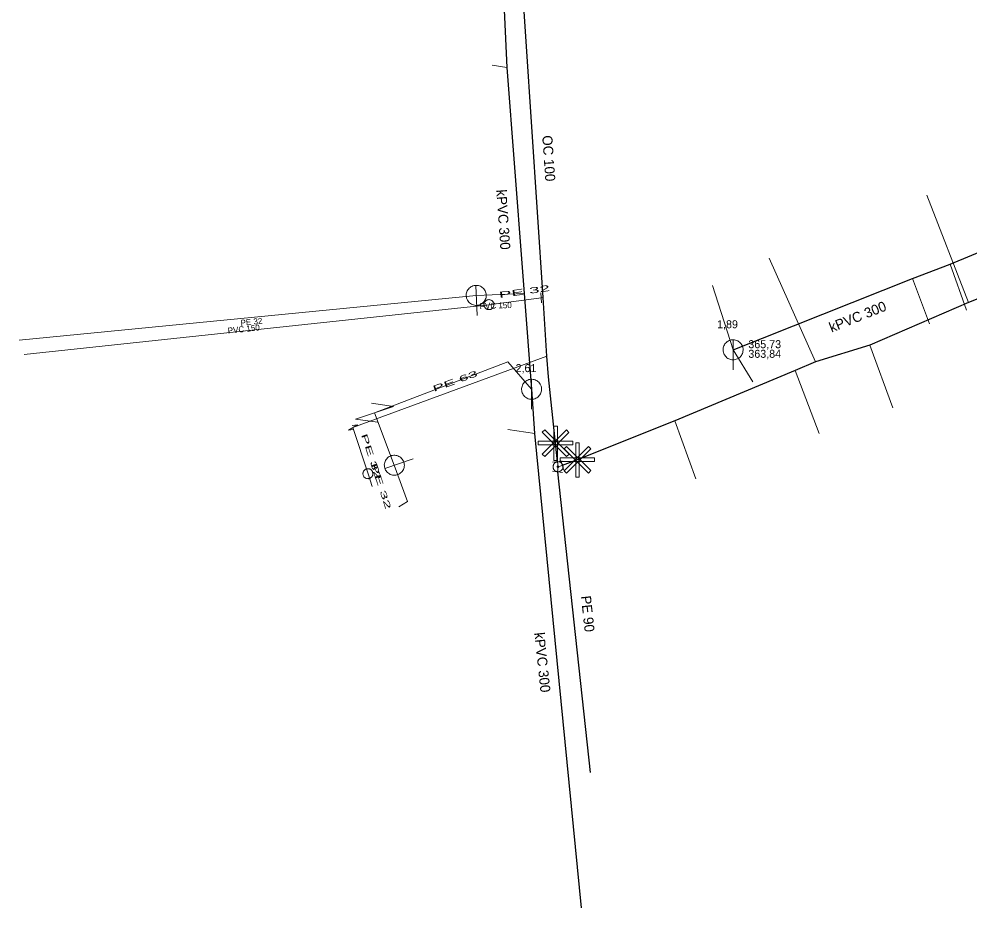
# Model space of a CAD drawing. Extents: x -809916 to -809489, y -991143 to -990912.
# Drawn here: x -809716.9 to -809621.9, y -991094.3 to -991005.4 of the extents above; entities that cross this region are included whole.
import ezdxf

# ---------------------------------------------------------------- set-up
doc = ezdxf.new("R2010")
doc.units = 0
doc.header["$LTSCALE"] = 0.32
doc.layers.add('1', color=7, linetype='Continuous')
for name, color, linetype, lineweight in [('11', 7, 'Continuous', 13), ('12', 7, 'Continuous', 13), ('13', 7, 'Continuous', 13), ('14', 7, 'Continuous', 25), ('17', 7, 'Continuous', 25), ('19', 7, 'Continuous', 13), ('22', 7, 'Continuous', 13), ('23', 7, 'Continuous', 13), ('31', 7, 'Continuous', 13), ('34', 7, 'Continuous', 13), ('47', 7, 'Continuous', 13)]:
    doc.layers.add(name, color=color, linetype=linetype, lineweight=lineweight)

msp = doc.modelspace()

# ---------------------------------------------------------------- linework, layer by layer
at = {"layer": '11'}
for p, q in [((-809669.64, -991010.07), (-809668.193, -991010.278)), ((-809622.243, -991034.537), (-809623.903, -991029.949)), ((-809625.96, -991035.892), (-809627.638, -991031.374)), ((-809647.623, -991032.088), (-809645.575, -991038.5)), ((-809716.921, -991037.548), (-809671.24, -991033.063)), ((-809671.24, -991033.063), (-809666.449, -991032.861)), ((-809643.62, -991041.703), (-809645.575, -991038.5)), ((-809679.424, -991050.034), (-809681.405, -991044.785)), ((-809668.083, -991046.469), (-809665.401, -991046.877))]:
    msp.add_line(p, q, dxfattribs=at)
for points in [[(-809681.405, -991044.785), (-809668.079, -991039.712), (-809665.71, -991042.44)], [(-809678.962, -991054.193), (-809678.104, -991053.665), (-809679.424, -991050.034)]]:
    msp.add_lwpolyline(points, dxfattribs=at)
at = {"layer": '12'}
for points in [[(-809662.22, -991046.499), (-809661.972, -991046.747), (-809664.401, -991049.176), (-809664.647, -991048.928)], [(-809664.639, -991046.738), (-809664.392, -991046.49), (-809661.963, -991048.919), (-809662.21, -991049.167)], [(-809663.486, -991046.135), (-809663.136, -991046.135), (-809663.136, -991049.57), (-809663.486, -991049.57)], [(-809661.602, -991047.644), (-809661.602, -991047.994), (-809665.037, -991047.994), (-809665.037, -991047.644)], [(-809661.301, -991047.791), (-809660.951, -991047.791), (-809660.951, -991051.226), (-809661.301, -991051.226)], [(-809660.035, -991048.155), (-809659.787, -991048.403), (-809662.216, -991050.832), (-809662.463, -991050.584)], [(-809662.454, -991048.394), (-809662.207, -991048.146), (-809659.778, -991050.575), (-809660.025, -991050.823)], [(-809659.417, -991049.3), (-809659.417, -991049.65), (-809662.852, -991049.65), (-809662.852, -991049.3)]]:
    msp.add_lwpolyline(points, close=True, dxfattribs=at)
at = {"layer": '13'}
for p, q in [((-809622.052, -991033.77), (-809626.208, -991023.049)), ((-809637.348, -991039.711), (-809641.962, -991029.357)), ((-809664.752, -991033.305), (-809669.989, -991034.015)), ((-809669.989, -991034.015), (-809716.423, -991038.976)), ((-809631.922, -991038.029), (-809629.608, -991044.298)), ((-809639.388, -991040.574), (-809636.96, -991046.859)), ((-809651.392, -991045.595), (-809649.291, -991051.397))]:
    msp.add_line(p, q, dxfattribs=at)
msp.add_lwpolyline([(-809664.17, -991039.14), (-809683.557, -991046.261), (-809682.032, -991050.892), (-809681.636, -991052.146)], dxfattribs=at)
at = {"layer": '14', "lineweight": 13}
for p, q in [((-809664.559, -991033.289), (-809664.752, -991033.305)), ((-809663.069, -991050.189), (-809663.12, -991049.689)), ((-809663.069, -991050.189), (-809663.129, -991050.689)), ((-809663.069, -991050.189), (-809662.639, -991050.049))]:
    msp.add_line(p, q, dxfattribs=at)
at = {"layer": '14'}
for points in [[(-809668.578, -991001.644), (-809668.193, -991010.278), (-809666.649, -991030.266), (-809666.449, -991032.861), (-809665.71, -991042.44)], [(-809645.575, -991038.5), (-809627.638, -991031.374), (-809623.903, -991029.949), (-809619.972, -991028.327)], [(-809665.71, -991042.44), (-809665.402, -991046.877), (-809660.74, -991094.27)]]:
    msp.add_lwpolyline(points, dxfattribs=at)
at = {"layer": '17'}
msp.add_line((-809663.129, -991050.689), (-809659.85, -991080.729), dxfattribs=at)
for points in [[(-809663.12, -991049.689), (-809663.328, -991047.82), (-809664.033, -991041.203), (-809664.17, -991039.14), (-809664.559, -991033.289), (-809666.831, -990999.127), (-809667.227, -990980.191), (-809667.463, -990975.798), (-809668.285, -990965.145), (-809668.606, -990961.097)], [(-809566.909, -991012.119), (-809584.614, -991018.942), (-809585.199, -991019.149), (-809592.769, -991022.094), (-809597, -991024.013), (-809605.64, -991027.482), (-809607.317, -991028.215), (-809616.081, -991031.412), (-809622.052, -991033.77), (-809631.921, -991038.028), (-809637.348, -991039.71), (-809639.388, -991040.574), (-809651.392, -991045.594), (-809661.144, -991049.477), (-809662.639, -991050.049)]]:
    msp.add_lwpolyline(points, dxfattribs=at)
at = {"layer": '22'}
for p, q in [((-809671.156, -991035.061), (-809671.281, -991032.064)), ((-809645.575, -991040.5), (-809645.574, -991037.5)), ((-809665.71, -991044.44), (-809665.709, -991041.44)), ((-809677.525, -991049.404), (-809680.372, -991050.348))]:
    msp.add_line(p, q, dxfattribs=at)
for points in [[(-809670.24, -991033.021), (-809670.251, -991032.912), (-809670.273, -991032.805), (-809670.308, -991032.701), (-809670.352, -991032.601), (-809670.408, -991032.507), (-809670.474, -991032.419), (-809670.549, -991032.339), (-809670.632, -991032.269), (-809670.723, -991032.207), (-809670.819, -991032.156), (-809670.921, -991032.115), (-809671.027, -991032.086), (-809671.135, -991032.069), (-809671.244, -991032.063), (-809671.354, -991032.07), (-809671.462, -991032.088), (-809671.567, -991032.118), (-809671.669, -991032.159), (-809671.765, -991032.212), (-809671.854, -991032.274), (-809671.937, -991032.347), (-809672.011, -991032.427), (-809672.076, -991032.516), (-809672.131, -991032.61), (-809672.175, -991032.71), (-809672.208, -991032.814), (-809672.229, -991032.922), (-809672.239, -991033.031), (-809672.236, -991033.141), (-809672.222, -991033.249), (-809672.196, -991033.355), (-809672.158, -991033.458), (-809672.11, -991033.556), (-809672.051, -991033.649), (-809671.981, -991033.734), (-809671.904, -991033.811), (-809671.818, -991033.879), (-809671.725, -991033.937), (-809671.627, -991033.985), (-809671.524, -991034.022), (-809671.417, -991034.047), (-809671.309, -991034.061), (-809671.199, -991034.062), (-809671.09, -991034.052), (-809670.983, -991034.029), (-809670.879, -991033.996), (-809670.779, -991033.95), (-809670.684, -991033.894), (-809670.597, -991033.829), (-809670.517, -991033.754), (-809670.445, -991033.671), (-809670.384, -991033.581), (-809670.332, -991033.484), (-809670.292, -991033.383), (-809670.263, -991033.277), (-809670.245, -991033.168), (-809670.24, -991033.059)], [(-809644.575, -991038.5), (-809644.58, -991038.391), (-809644.598, -991038.283), (-809644.628, -991038.177), (-809644.668, -991038.076), (-809644.72, -991037.979), (-809644.782, -991037.889), (-809644.854, -991037.806), (-809644.934, -991037.732), (-809645.022, -991037.666), (-809645.116, -991037.611), (-809645.216, -991037.566), (-809645.321, -991037.533), (-809645.428, -991037.511), (-809645.537, -991037.501), (-809645.647, -991037.503), (-809645.755, -991037.517), (-809645.862, -991037.542), (-809645.965, -991037.579), (-809646.063, -991037.628), (-809646.155, -991037.686), (-809646.241, -991037.755), (-809646.318, -991037.832), (-809646.387, -991037.918), (-809646.446, -991038.01), (-809646.494, -991038.108), (-809646.531, -991038.211), (-809646.557, -991038.318), (-809646.571, -991038.426), (-809646.574, -991038.536), (-809646.564, -991038.645), (-809646.543, -991038.752), (-809646.509, -991038.856), (-809646.465, -991038.956), (-809646.41, -991039.051), (-809646.344, -991039.139), (-809646.27, -991039.219), (-809646.187, -991039.291), (-809646.097, -991039.353), (-809646.001, -991039.405), (-809645.899, -991039.446), (-809645.794, -991039.476), (-809645.686, -991039.494), (-809645.576, -991039.5), (-809645.467, -991039.494), (-809645.359, -991039.476), (-809645.254, -991039.447), (-809645.152, -991039.406), (-809645.055, -991039.354), (-809644.965, -991039.292), (-809644.882, -991039.221), (-809644.807, -991039.141), (-809644.742, -991039.053), (-809644.686, -991038.959), (-809644.642, -991038.859), (-809644.608, -991038.755), (-809644.586, -991038.647), (-809644.576, -991038.538)], [(-809664.71, -991042.44), (-809664.715, -991042.331), (-809664.733, -991042.223), (-809664.763, -991042.117), (-809664.803, -991042.016), (-809664.855, -991041.919), (-809664.917, -991041.829), (-809664.989, -991041.746), (-809665.069, -991041.672), (-809665.157, -991041.606), (-809665.251, -991041.551), (-809665.351, -991041.506), (-809665.456, -991041.473), (-809665.563, -991041.451), (-809665.672, -991041.441), (-809665.782, -991041.443), (-809665.89, -991041.457), (-809665.997, -991041.482), (-809666.1, -991041.519), (-809666.198, -991041.568), (-809666.29, -991041.626), (-809666.376, -991041.695), (-809666.453, -991041.772), (-809666.522, -991041.858), (-809666.581, -991041.95), (-809666.629, -991042.048), (-809666.666, -991042.151), (-809666.692, -991042.258), (-809666.706, -991042.366), (-809666.709, -991042.476), (-809666.699, -991042.585), (-809666.678, -991042.692), (-809666.644, -991042.796), (-809666.6, -991042.896), (-809666.545, -991042.991), (-809666.479, -991043.079), (-809666.405, -991043.159), (-809666.322, -991043.231), (-809666.232, -991043.293), (-809666.136, -991043.345), (-809666.034, -991043.386), (-809665.929, -991043.416), (-809665.821, -991043.434), (-809665.711, -991043.44), (-809665.602, -991043.434), (-809665.494, -991043.416), (-809665.389, -991043.387), (-809665.287, -991043.346), (-809665.19, -991043.294), (-809665.1, -991043.232), (-809665.017, -991043.161), (-809664.942, -991043.081), (-809664.877, -991042.993), (-809664.821, -991042.899), (-809664.777, -991042.799), (-809664.743, -991042.695), (-809664.721, -991042.587), (-809664.711, -991042.478)], [(-809679.738, -991049.084), (-809679.839, -991049.124), (-809679.936, -991049.175), (-809680.027, -991049.237), (-809680.111, -991049.307), (-809680.186, -991049.387), (-809680.252, -991049.474), (-809680.308, -991049.568), (-809680.353, -991049.668), (-809680.388, -991049.772), (-809680.411, -991049.878), (-809680.422, -991049.988), (-809680.421, -991050.098), (-809680.408, -991050.206), (-809680.383, -991050.313), (-809680.346, -991050.416), (-809680.299, -991050.515), (-809680.242, -991050.608), (-809680.174, -991050.694), (-809680.097, -991050.772), (-809680.013, -991050.841), (-809679.92, -991050.901), (-809679.823, -991050.95), (-809679.72, -991050.988), (-809679.614, -991051.015), (-809679.506, -991051.03), (-809679.396, -991051.033), (-809679.286, -991051.024), (-809679.179, -991051.003), (-809679.074, -991050.97), (-809678.974, -991050.926), (-809678.879, -991050.873), (-809678.791, -991050.808), (-809678.71, -991050.735), (-809678.637, -991050.652), (-809678.574, -991050.562), (-809678.522, -991050.467), (-809678.48, -991050.365), (-809678.449, -991050.26), (-809678.43, -991050.153), (-809678.423, -991050.043), (-809678.428, -991049.934), (-809678.445, -991049.826), (-809678.474, -991049.72), (-809678.514, -991049.618), (-809678.565, -991049.521), (-809678.625, -991049.431), (-809678.696, -991049.347), (-809678.776, -991049.271), (-809678.863, -991049.205), (-809678.957, -991049.149), (-809679.056, -991049.103), (-809679.16, -991049.069), (-809679.267, -991049.045), (-809679.376, -991049.035), (-809679.485, -991049.035), (-809679.595, -991049.048), (-809679.701, -991049.073)]]:
    msp.add_lwpolyline(points, close=True, dxfattribs=at)
at = {"layer": '23'}
for points in [[(-809669.737, -991033.546), (-809669.784, -991033.524), (-809669.834, -991033.508), (-809669.884, -991033.495), (-809669.938, -991033.49), (-809669.989, -991033.49), (-809670.041, -991033.494), (-809670.092, -991033.505), (-809670.142, -991033.52), (-809670.191, -991033.541), (-809670.236, -991033.567), (-809670.279, -991033.597), (-809670.318, -991033.631), (-809670.353, -991033.671), (-809670.385, -991033.712), (-809670.411, -991033.756), (-809670.434, -991033.805), (-809670.45, -991033.855), (-809670.461, -991033.906), (-809670.466, -991033.958), (-809670.468, -991034.009), (-809670.464, -991034.061), (-809670.453, -991034.113), (-809670.438, -991034.164), (-809670.416, -991034.21), (-809670.391, -991034.256), (-809670.361, -991034.299), (-809670.325, -991034.338), (-809670.287, -991034.373), (-809670.245, -991034.404), (-809670.2, -991034.431), (-809670.153, -991034.453), (-809670.103, -991034.471), (-809670.051, -991034.482), (-809670, -991034.488), (-809669.948, -991034.488), (-809669.897, -991034.484), (-809669.844, -991034.473), (-809669.795, -991034.458), (-809669.746, -991034.436)], [(-809670.464, -991034.061), (-809670.453, -991034.113), (-809670.438, -991034.164), (-809670.416, -991034.21), (-809670.391, -991034.256), (-809670.361, -991034.299), (-809670.325, -991034.338), (-809670.287, -991034.373), (-809670.245, -991034.404), (-809670.2, -991034.431), (-809670.153, -991034.453), (-809670.103, -991034.471), (-809670.051, -991034.482), (-809670, -991034.488), (-809669.948, -991034.488), (-809669.897, -991034.484), (-809669.844, -991034.473), (-809669.795, -991034.458), (-809669.746, -991034.436), (-809669.701, -991034.412), (-809669.658, -991034.382), (-809669.619, -991034.345), (-809669.583, -991034.307), (-809669.552, -991034.265), (-809669.525, -991034.22), (-809669.504, -991034.173), (-809669.487, -991034.123), (-809669.476, -991034.073), (-809669.47, -991034.02), (-809669.47, -991033.968), (-809669.474, -991033.916), (-809669.484, -991033.865), (-809669.5, -991033.814), (-809669.521, -991033.766), (-809669.546, -991033.721), (-809669.577, -991033.68), (-809669.611, -991033.64), (-809669.65, -991033.604), (-809669.692, -991033.572), (-809669.737, -991033.546)], [(-809669.746, -991034.436), (-809669.701, -991034.412), (-809669.658, -991034.382), (-809669.619, -991034.345), (-809669.583, -991034.307), (-809669.552, -991034.265), (-809669.525, -991034.22), (-809669.504, -991034.173), (-809669.487, -991034.123), (-809669.476, -991034.073), (-809669.47, -991034.02), (-809669.47, -991033.968), (-809669.474, -991033.916), (-809669.484, -991033.865), (-809669.5, -991033.814), (-809669.521, -991033.766), (-809669.546, -991033.721), (-809669.577, -991033.68), (-809669.611, -991033.64), (-809669.65, -991033.604), (-809669.692, -991033.572), (-809669.737, -991033.546), (-809669.784, -991033.524), (-809669.834, -991033.508), (-809669.884, -991033.495), (-809669.938, -991033.49), (-809669.989, -991033.49), (-809670.041, -991033.494), (-809670.092, -991033.505), (-809670.142, -991033.52), (-809670.191, -991033.541), (-809670.236, -991033.567), (-809670.279, -991033.597), (-809670.318, -991033.631), (-809670.353, -991033.671), (-809670.385, -991033.712), (-809670.411, -991033.756), (-809670.434, -991033.805), (-809670.45, -991033.855), (-809670.461, -991033.906)], [(-809670.461, -991033.906), (-809670.466, -991033.958), (-809670.468, -991034.009), (-809670.464, -991034.061)], [(-809681.663, -991050.573), (-809681.695, -991050.535), (-809681.733, -991050.498), (-809681.776, -991050.466), (-809681.82, -991050.439), (-809681.868, -991050.416), (-809681.917, -991050.397), (-809681.967, -991050.386), (-809682.02, -991050.379), (-809682.071, -991050.377), (-809682.124, -991050.381), (-809682.175, -991050.391), (-809682.225, -991050.405), (-809682.274, -991050.424), (-809682.32, -991050.449), (-809682.364, -991050.479), (-809682.403, -991050.512), (-809682.438, -991050.55), (-809682.471, -991050.592), (-809682.499, -991050.636), (-809682.522, -991050.684), (-809682.539, -991050.733), (-809682.552, -991050.783), (-809682.558, -991050.836), (-809682.561, -991050.887), (-809682.556, -991050.94), (-809682.546, -991050.991), (-809682.532, -991051.041), (-809682.512, -991051.089), (-809682.488, -991051.136), (-809682.458, -991051.18), (-809682.424, -991051.219), (-809682.386, -991051.256), (-809682.346, -991051.288), (-809682.3, -991051.314), (-809682.254, -991051.338), (-809682.205, -991051.355), (-809682.153, -991051.368), (-809682.101, -991051.375), (-809682.049, -991051.376)], [(-809682.539, -991050.733), (-809682.552, -991050.783), (-809682.558, -991050.836), (-809682.561, -991050.887), (-809682.556, -991050.94), (-809682.546, -991050.991), (-809682.532, -991051.041), (-809682.512, -991051.089), (-809682.488, -991051.136), (-809682.458, -991051.18), (-809682.424, -991051.219), (-809682.386, -991051.256), (-809682.346, -991051.288), (-809682.3, -991051.314), (-809682.254, -991051.338), (-809682.205, -991051.355), (-809682.153, -991051.368), (-809682.101, -991051.375), (-809682.049, -991051.376), (-809681.997, -991051.372), (-809681.946, -991051.363), (-809681.896, -991051.349), (-809681.847, -991051.329), (-809681.8, -991051.304), (-809681.759, -991051.274), (-809681.718, -991051.241), (-809681.682, -991051.203), (-809681.65, -991051.161), (-809681.623, -991051.117), (-809681.6, -991051.07), (-809681.582, -991051.021), (-809681.57, -991050.97), (-809681.562, -991050.918), (-809681.561, -991050.865), (-809681.565, -991050.813), (-809681.574, -991050.763), (-809681.588, -991050.713), (-809681.609, -991050.663), (-809681.632, -991050.618), (-809681.663, -991050.573)], [(-809681.896, -991051.349), (-809681.847, -991051.329), (-809681.8, -991051.304), (-809681.759, -991051.274), (-809681.718, -991051.241), (-809681.682, -991051.203), (-809681.65, -991051.161), (-809681.623, -991051.117), (-809681.6, -991051.07), (-809681.582, -991051.021), (-809681.57, -991050.97), (-809681.562, -991050.918), (-809681.561, -991050.865), (-809681.565, -991050.813), (-809681.574, -991050.763), (-809681.588, -991050.713), (-809681.609, -991050.663), (-809681.632, -991050.618), (-809681.663, -991050.573), (-809681.695, -991050.535), (-809681.733, -991050.498), (-809681.776, -991050.466), (-809681.82, -991050.439), (-809681.868, -991050.416), (-809681.917, -991050.397), (-809681.967, -991050.386), (-809682.02, -991050.379), (-809682.071, -991050.377), (-809682.124, -991050.381), (-809682.175, -991050.391), (-809682.225, -991050.405), (-809682.274, -991050.424), (-809682.32, -991050.449), (-809682.364, -991050.479), (-809682.403, -991050.512), (-809682.438, -991050.55), (-809682.471, -991050.592), (-809682.499, -991050.636), (-809682.522, -991050.684), (-809682.539, -991050.733)], [(-809682.049, -991051.376), (-809681.997, -991051.372), (-809681.946, -991051.363), (-809681.896, -991051.349)]]:
    msp.add_lwpolyline(points, dxfattribs=at)
at = {"layer": '31'}
msp.add_lwpolyline([(-809681.089, -991045.734), (-809683.302, -991045.414), (-809679.506, -991044.155), (-809681.719, -991043.835)], dxfattribs=at)
at = {"layer": '34'}
for p, q in [((-809664.712, -991033.803), (-809664.79, -991032.806)), ((-809662.622, -991049.638), (-809663.617, -991049.738)), ((-809662.794, -991049.573), (-809662.484, -991050.524)), ((-809663.625, -991050.629), (-809662.632, -991050.749))]:
    msp.add_line(p, q, dxfattribs=at)
at = {"layer": '47'}
msp.add_line((-809683.114, -991046.008), (-809683.621, -991046.07), dxfattribs=at)
msp.add_lwpolyline([(-809683.114, -991046.008), (-809683.999, -991046.513), (-809683.492, -991046.451)], dxfattribs=at)
for points in [[(-809663.458, -991049.875), (-809663.488, -991049.917), (-809663.515, -991049.963), (-809663.535, -991050.011), (-809663.552, -991050.06), (-809663.563, -991050.112), (-809663.568, -991050.164), (-809663.567, -991050.216), (-809663.561, -991050.268), (-809663.551, -991050.319), (-809663.535, -991050.369), (-809663.513, -991050.417), (-809663.486, -991050.462), (-809663.456, -991050.504), (-809663.421, -991050.543), (-809663.382, -991050.578), (-809663.34, -991050.608), (-809663.294, -991050.635), (-809663.245, -991050.656), (-809663.197, -991050.672), (-809663.145, -991050.683), (-809663.093, -991050.688), (-809663.04, -991050.688), (-809662.988, -991050.682), (-809662.937, -991050.671), (-809662.888, -991050.655), (-809662.84, -991050.633), (-809662.794, -991050.607), (-809662.753, -991050.576), (-809662.714, -991050.541), (-809662.679, -991050.502), (-809662.649, -991050.46), (-809662.622, -991050.414), (-809662.6, -991050.366), (-809662.585, -991050.317), (-809662.574, -991050.265), (-809662.569, -991050.213), (-809662.569, -991050.161), (-809662.574, -991050.109), (-809662.586, -991050.057), (-809662.602, -991050.008), (-809662.624, -991049.96), (-809662.649, -991049.915), (-809662.681, -991049.873), (-809662.716, -991049.834), (-809662.755, -991049.799), (-809662.797, -991049.769), (-809662.843, -991049.742), (-809662.89, -991049.721), (-809662.94, -991049.705), (-809662.992, -991049.694), (-809663.044, -991049.689), (-809663.096, -991049.689), (-809663.148, -991049.695), (-809663.199, -991049.706), (-809663.249, -991049.722), (-809663.297, -991049.744), (-809663.341, -991049.77), (-809663.384, -991049.801), (-809663.423, -991049.836)], [(-809663.132, -991050.137), (-809663.138, -991050.144), (-809663.141, -991050.152), (-809663.145, -991050.159), (-809663.148, -991050.167), (-809663.15, -991050.176), (-809663.15, -991050.185), (-809663.151, -991050.193), (-809663.15, -991050.202), (-809663.147, -991050.21), (-809663.145, -991050.218), (-809663.141, -991050.226), (-809663.137, -991050.234), (-809663.132, -991050.24), (-809663.127, -991050.247), (-809663.12, -991050.252), (-809663.113, -991050.258), (-809663.105, -991050.261), (-809663.098, -991050.265), (-809663.09, -991050.268), (-809663.081, -991050.27), (-809663.072, -991050.27), (-809663.064, -991050.271), (-809663.055, -991050.27), (-809663.046, -991050.268), (-809663.039, -991050.265), (-809663.031, -991050.261), (-809663.023, -991050.257), (-809663.017, -991050.252), (-809663.01, -991050.247), (-809663.005, -991050.24), (-809662.999, -991050.233), (-809662.996, -991050.225), (-809662.992, -991050.218), (-809662.989, -991050.21), (-809662.987, -991050.201), (-809662.986, -991050.193), (-809662.986, -991050.184), (-809662.987, -991050.175), (-809662.989, -991050.166), (-809662.992, -991050.159), (-809662.996, -991050.151), (-809663, -991050.143), (-809663.005, -991050.137), (-809663.01, -991050.13), (-809663.017, -991050.125), (-809663.024, -991050.119), (-809663.032, -991050.116), (-809663.039, -991050.112), (-809663.047, -991050.109), (-809663.056, -991050.107), (-809663.064, -991050.106), (-809663.073, -991050.106), (-809663.082, -991050.107), (-809663.09, -991050.11), (-809663.098, -991050.112), (-809663.106, -991050.116), (-809663.114, -991050.12), (-809663.12, -991050.125), (-809663.127, -991050.13)]]:
    msp.add_lwpolyline(points, close=True, dxfattribs=at)

# ---------------------------------------------------------------- texts
at = {"layer": '1'}
for s, height, rotation, p in [('OC 100', 1, 274, (-809664.648, -991017.105)), ('kPVC 300', 1, 274, (-809669.238, -991022.523)), ('PVC 150 ', 0.6, 2, (-809670.884, -991034.439)), ('kPVC 300', 1, 22, (-809635.737, -991036.786)), ('PE 32 ', 0.6, 6, (-809694.754, -991036.116)), ('PVC 150 ', 0.6, 6, (-809696.034, -991036.894)), ('PE 90 ', 1, 276, (-809660.781, -991063.117)), ('kPVC 300', 1, 276, (-809665.438, -991066.786))]:
    msp.add_text(s, height=height, rotation=rotation, dxfattribs=at).set_placement(p)
for s, rotation, width, p in [('PE 32 ', 8, 2.35, (-809668.929, -991033.324)), ('PE 63 ', 20, 2.15, (-809675.458, -991042.709)), ('PE 32 ', 288, 2.2, (-809682.75, -991046.982)), ('PE 32 ', 288, 2.2, (-809681.769, -991049.925))]:
    msp.add_text(s, height=0.6, rotation=rotation, dxfattribs=dict(at, width=width)).set_placement(p)
for s, p in [('1,89', (-809647.175, -991036.348)), ('2,61', (-809667.31, -991040.728))]:
    msp.add_text(s, height=0.8, dxfattribs=at).set_placement(p)
at = {"layer": '19'}
for s, p in [('365,73', (-809644.053, -991038.34)), ('363,84', (-809644.053, -991039.3))]:
    msp.add_text(s, height=0.8, dxfattribs=at).set_placement(p)

doc.saveas('drawing.dxf')
